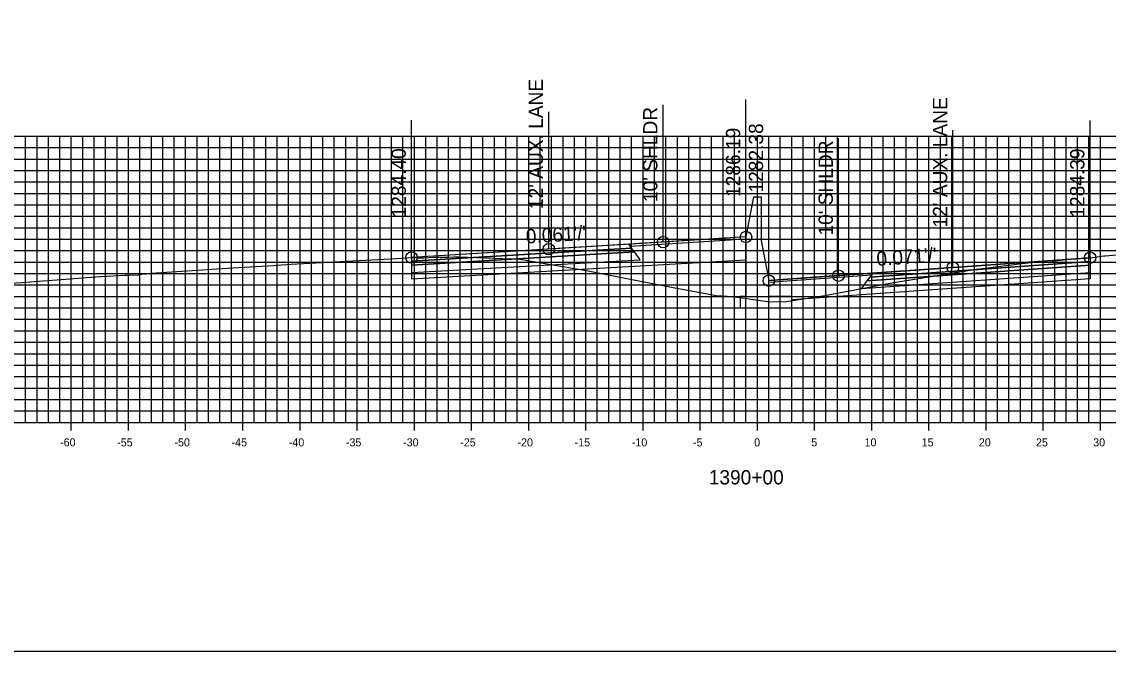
# Model space of a CAD drawing. Extents: x 674939 to 678919, y 750652 to 765176.
# Drawn here: x 678674.2 to 678769.2, y 755752.6 to 755807.6 of the extents above; entities that cross this region are included whole.
import ezdxf

# ---------------------------------------------------------------- set-up
doc = ezdxf.new("R2010")
doc.units = 0
for name, color, linetype in [('R_Alt Surface', 7, 'Continuous'), ('R_Axis', 7, 'Continuous'), ('R_Axis Annot', 7, 'Continuous'), ('R_Exist Surface', 7, 'Continuous'), ('R_Fin Surface', 7, 'Continuous'), ('R_Grid', 7, 'Continuous'), ('R_No Plot', 7, 'Continuous'), ('R_Proposed Road', 7, 'Continuous'), ('R_Xsect Elev', 7, 'Continuous'), ('R_Xsect Slope', 7, 'Continuous')]:
    doc.layers.add(name, color=color, linetype=linetype)

msp = doc.modelspace()

# ---------------------------------------------------------------- linework, layer by layer
at = {"layer": 'R_Alt Surface'}
for points in [[(678708.288, 755786.621), (678708.288, 755786.291), (678727.788, 755787.437), (678727.538, 755787.777)], [(678708.288, 755786.291), (678708.288, 755785.631), (678728.288, 755786.757), (678727.788, 755787.437)], [(678767.633, 755786.277), (678767.633, 755785.617), (678747.633, 755784.223), (678748.133, 755784.903)], [(678767.633, 755786.607), (678767.633, 755786.277), (678748.133, 755784.903), (678748.383, 755785.243)]]:
    msp.add_lwpolyline(points, close=True, dxfattribs=at)
for points in [[(678708.288, 755785.631), (678708.288, 755785.091), (678728.288, 755786.217)], [(678728.288, 755786.217), (678737.533, 755786.737)], [(678767.633, 755785.617), (678767.635, 755785.077), (678747.633, 755783.683)], [(678747.633, 755783.683), (678741.533, 755783.258)]]:
    msp.add_lwpolyline(points, dxfattribs=at)
at = {"layer": 'R_Axis'}
for p, q in [((678678.533, 755771.851), (678678.533, 755773.251)), ((678683.533, 755771.851), (678683.533, 755773.251)), ((678688.533, 755771.851), (678688.533, 755773.251)), ((678693.533, 755771.851), (678693.533, 755773.251)), ((678698.533, 755771.851), (678698.533, 755773.251)), ((678703.533, 755771.851), (678703.533, 755773.251)), ((678708.533, 755771.851), (678708.533, 755773.251)), ((678713.533, 755771.851), (678713.533, 755773.251)), ((678718.533, 755771.851), (678718.533, 755773.251)), ((678723.533, 755771.851), (678723.533, 755773.251)), ((678728.533, 755771.851), (678728.533, 755773.251)), ((678733.533, 755771.851), (678733.533, 755773.251)), ((678738.533, 755771.851), (678738.533, 755773.251)), ((678743.533, 755771.851), (678743.533, 755773.251)), ((678748.533, 755771.851), (678748.533, 755773.251)), ((678753.533, 755771.851), (678753.533, 755773.251)), ((678758.533, 755771.851), (678758.533, 755773.251)), ((678763.533, 755771.851), (678763.533, 755773.251)), ((678768.533, 755771.851), (678768.533, 755773.251)), ((678638.533, 755772.551), (678838.533, 755772.551))]:
    msp.add_line(p, q, dxfattribs=at)
at = {"layer": 'R_Exist Surface'}
msp.add_lwpolyline([(678673.14, 755784.719), (678674.273, 755784.782), (678674.496, 755784.805), (678678.046, 755785.064), (678679.84, 755785.197), (678681.116, 755785.282), (678683.24, 755785.414), (678683.616, 755785.424), (678684.365, 755785.451), (678684.741, 755785.489), (678685.122, 755785.53), (678685.274, 755785.545), (678685.515, 755785.57), (678689.115, 755785.817), (678691.696, 755785.985), (678694.663, 755786.16), (678696.269, 755786.26), (678696.516, 755786.28), (678697.748, 755786.363), (678701.523, 755786.574), (678707.514, 755786.908), (678708.288, 755786.951), (678708.292, 755786.951), (678708.439, 755786.96), (678708.805, 755786.934), (678709.35, 755786.928), (678710.205, 755786.968), (678710.595, 755786.986), (678711.448, 755786.994), (678711.995, 755787.001), (678712.32, 755787.001), (678712.424, 755787.004), (678716.253, 755786.868), (678717.771, 755786.809), (678718.766, 755786.644), (678723.748, 755785.775), (678727.11, 755785.112), (678731.173, 755784.334), (678734.932, 755783.62), (678736.385, 755783.554), (678739.626, 755783.074), (678741.069, 755783.108), (678744.445, 755783.623), (678750.294, 755784.75), (678756.263, 755785.709), (678757.67, 755785.939), (678758.226, 755786.002), (678761.661, 755786.416), (678764.041, 755786.695), (678764.053, 755786.695), (678764.491, 755786.644), (678764.578, 755786.653), (678765.516, 755786.767), (678765.555, 755786.771), (678765.58, 755786.772), (678767.264, 755786.889), (678767.329, 755786.897), (678767.633, 755786.937), (678768.822, 755787.098), (678768.944, 755787.112), (678773.028, 755787.435)], dxfattribs=at)
at = {"layer": 'R_Fin Surface'}
for points in [[(678737.533, 755788.745), (678730.288, 755788.301), (678720.288, 755787.687), (678708.288, 755786.951)], [(678767.633, 755786.937), (678755.633, 755786.082), (678745.633, 755785.369), (678739.533, 755784.934)]]:
    msp.add_lwpolyline(points, dxfattribs=at)
for points in [[(678708.288, 755786.951), (678708.288, 755786.621), (678727.538, 755787.777), (678727.288, 755788.117)], [(678727.406, 755787.956), (678737.533, 755788.585), (678737.533, 755788.745), (678727.288, 755788.117)], [(678767.633, 755786.937), (678767.633, 755786.607), (678748.383, 755785.243), (678748.633, 755785.583)], [(678748.515, 755785.423), (678739.533, 755784.774), (678739.533, 755784.934), (678748.633, 755785.583)]]:
    msp.add_lwpolyline(points, close=True, dxfattribs=at)
at = {"layer": 'R_Grid'}
for p, q in [((678638.533, 755797.551), (678838.533, 755797.551)), ((678674.533, 755772.551), (678674.533, 755797.551)), ((678675.533, 755772.551), (678675.533, 755797.551)), ((678676.533, 755772.551), (678676.533, 755797.551)), ((678677.533, 755772.551), (678677.533, 755797.551)), ((678678.533, 755772.551), (678678.533, 755797.551)), ((678679.533, 755772.551), (678679.533, 755797.551)), ((678680.533, 755772.551), (678680.533, 755797.551)), ((678681.533, 755772.551), (678681.533, 755797.551)), ((678682.533, 755772.551), (678682.533, 755797.551)), ((678683.533, 755772.551), (678683.533, 755797.551)), ((678684.533, 755772.551), (678684.533, 755797.551)), ((678685.533, 755772.551), (678685.533, 755797.551)), ((678686.533, 755772.551), (678686.533, 755797.551)), ((678687.533, 755772.551), (678687.533, 755797.551)), ((678688.533, 755772.551), (678688.533, 755797.551)), ((678689.533, 755772.551), (678689.533, 755797.551)), ((678690.533, 755772.551), (678690.533, 755797.551)), ((678691.533, 755772.551), (678691.533, 755797.551)), ((678692.533, 755772.551), (678692.533, 755797.551)), ((678693.533, 755772.551), (678693.533, 755797.551)), ((678694.533, 755772.551), (678694.533, 755797.551)), ((678695.533, 755772.551), (678695.533, 755797.551)), ((678696.533, 755772.551), (678696.533, 755797.551)), ((678697.533, 755772.551), (678697.533, 755797.551)), ((678698.533, 755772.551), (678698.533, 755797.551)), ((678699.533, 755772.551), (678699.533, 755797.551)), ((678700.533, 755772.551), (678700.533, 755797.551)), ((678701.533, 755772.551), (678701.533, 755797.551)), ((678702.533, 755772.551), (678702.533, 755797.551)), ((678703.533, 755772.551), (678703.533, 755797.551)), ((678704.533, 755772.551), (678704.533, 755797.551)), ((678705.533, 755772.551), (678705.533, 755797.551)), ((678706.533, 755772.551), (678706.533, 755797.551)), ((678707.533, 755772.551), (678707.533, 755797.551)), ((678708.533, 755772.551), (678708.533, 755797.551)), ((678709.533, 755772.551), (678709.533, 755797.551)), ((678710.533, 755772.551), (678710.533, 755797.551)), ((678711.533, 755772.551), (678711.533, 755797.551)), ((678712.533, 755772.551), (678712.533, 755797.551)), ((678713.533, 755772.551), (678713.533, 755797.551)), ((678714.533, 755772.551), (678714.533, 755797.551)), ((678715.533, 755772.551), (678715.533, 755797.551)), ((678716.533, 755772.551), (678716.533, 755797.551)), ((678717.533, 755772.551), (678717.533, 755797.551)), ((678718.533, 755772.551), (678718.533, 755797.551)), ((678719.533, 755772.551), (678719.533, 755797.551)), ((678720.533, 755772.551), (678720.533, 755797.551)), ((678721.533, 755772.551), (678721.533, 755797.551)), ((678722.533, 755772.551), (678722.533, 755797.551)), ((678723.533, 755772.551), (678723.533, 755797.551)), ((678724.533, 755772.551), (678724.533, 755797.551)), ((678725.533, 755772.551), (678725.533, 755797.551)), ((678726.533, 755772.551), (678726.533, 755797.551)), ((678727.533, 755772.551), (678727.533, 755797.551)), ((678728.533, 755772.551), (678728.533, 755797.551)), ((678729.533, 755772.551), (678729.533, 755797.551)), ((678730.533, 755772.551), (678730.533, 755797.551)), ((678731.533, 755772.551), (678731.533, 755797.551)), ((678732.533, 755772.551), (678732.533, 755797.551)), ((678733.533, 755772.551), (678733.533, 755797.551)), ((678734.533, 755772.551), (678734.533, 755797.551)), ((678735.533, 755772.551), (678735.533, 755797.551)), ((678736.533, 755772.551), (678736.533, 755797.551)), ((678737.533, 755772.551), (678737.533, 755797.551)), ((678738.533, 755772.551), (678738.533, 755797.551)), ((678739.533, 755772.551), (678739.533, 755797.551)), ((678740.533, 755772.551), (678740.533, 755797.551)), ((678741.533, 755772.551), (678741.533, 755797.551)), ((678742.533, 755772.551), (678742.533, 755797.551)), ((678743.533, 755772.551), (678743.533, 755797.551)), ((678744.533, 755772.551), (678744.533, 755797.551)), ((678745.533, 755772.551), (678745.533, 755797.551)), ((678746.533, 755772.551), (678746.533, 755797.551)), ((678747.533, 755772.551), (678747.533, 755797.551)), ((678748.533, 755772.551), (678748.533, 755797.551)), ((678749.533, 755772.551), (678749.533, 755797.551)), ((678750.533, 755772.551), (678750.533, 755797.551)), ((678751.533, 755772.551), (678751.533, 755797.551)), ((678752.533, 755772.551), (678752.533, 755797.551)), ((678753.533, 755772.551), (678753.533, 755797.551)), ((678754.533, 755772.551), (678754.533, 755797.551)), ((678755.533, 755772.551), (678755.533, 755797.551)), ((678756.533, 755772.551), (678756.533, 755797.551)), ((678757.533, 755772.551), (678757.533, 755797.551)), ((678758.533, 755772.551), (678758.533, 755797.551)), ((678759.533, 755772.551), (678759.533, 755797.551)), ((678760.533, 755772.551), (678760.533, 755797.551)), ((678761.533, 755772.551), (678761.533, 755797.551)), ((678762.533, 755772.551), (678762.533, 755797.551)), ((678763.533, 755772.551), (678763.533, 755797.551)), ((678764.533, 755772.551), (678764.533, 755797.551)), ((678765.533, 755772.551), (678765.533, 755797.551)), ((678766.533, 755772.551), (678766.533, 755797.551)), ((678767.533, 755772.551), (678767.533, 755797.551)), ((678768.533, 755772.551), (678768.533, 755797.551)), ((678638.533, 755796.551), (678838.533, 755796.551)), ((678638.533, 755795.551), (678838.533, 755795.551)), ((678638.533, 755794.551), (678838.533, 755794.551)), ((678638.533, 755793.551), (678838.533, 755793.551)), ((678638.533, 755792.551), (678838.533, 755792.551)), ((678638.533, 755791.551), (678838.533, 755791.551)), ((678638.533, 755790.551), (678838.533, 755790.551)), ((678638.533, 755789.551), (678838.533, 755789.551)), ((678638.533, 755788.551), (678838.533, 755788.551)), ((678638.533, 755787.551), (678838.533, 755787.551)), ((678638.533, 755786.551), (678838.533, 755786.551)), ((678638.533, 755785.551), (678838.533, 755785.551)), ((678638.533, 755784.551), (678838.533, 755784.551)), ((678638.533, 755783.551), (678838.533, 755783.551)), ((678638.533, 755782.551), (678838.533, 755782.551)), ((678638.533, 755781.551), (678838.533, 755781.551)), ((678638.533, 755780.551), (678838.533, 755780.551)), ((678638.533, 755779.551), (678838.533, 755779.551)), ((678638.533, 755778.551), (678838.533, 755778.551)), ((678638.533, 755777.551), (678838.533, 755777.551)), ((678638.533, 755776.551), (678838.533, 755776.551)), ((678638.533, 755775.551), (678838.533, 755775.551)), ((678638.533, 755774.551), (678838.533, 755774.551)), ((678638.533, 755773.551), (678838.533, 755773.551)), ((678638.533, 755772.551), (678838.533, 755772.551))]:
    msp.add_line(p, q, dxfattribs=at)
at = {"layer": 'R_No Plot'}
msp.add_lwpolyline([(678578.533, 755752.551), (678918.533, 755752.551), (678918.533, 755972.551), (678578.533, 755972.551)], close=True, dxfattribs=at)
for centre in [(678737.533, 755788.745), (678720.288, 755787.687), (678730.288, 755788.301), (678708.288, 755786.951), (678767.633, 755786.937), (678755.633, 755786.082), (678739.533, 755784.934), (678745.633, 755785.369)]:
    msp.add_circle(centre, 0.5, dxfattribs=at)
at = {"layer": 'R_Proposed Road'}
for points in [[(678738.203, 755792.245), (678737.533, 755788.745)], [(678738.203, 755792.245), (678738.203, 755792.245)], [(678738.203, 755792.245), (678738.863, 755792.245)], [(678738.863, 755792.245), (678738.863, 755788.434)], [(678737.533, 755788.745), (678737.533, 755783.559), (678737.033, 755783.559), (678737.033, 755782.559), (678741.533, 755782.559), (678741.533, 755783.559), (678739.533, 755783.559), (678739.533, 755784.934)], [(678738.863, 755788.434), (678739.533, 755784.934)]]:
    msp.add_lwpolyline(points, dxfattribs=at)
at = {"layer": 'R_Xsect Elev'}
for p, q in [((678737.533, 755788.745), (678737.533, 755800.745)), ((678720.288, 755787.687), (678720.288, 755799.687)), ((678730.288, 755788.301), (678730.288, 755800.301)), ((678708.288, 755786.951), (678708.288, 755798.951)), ((678767.633, 755786.937), (678767.633, 755798.937)), ((678755.633, 755786.082), (678755.633, 755798.082)), ((678739.533, 755784.934), (678739.533, 755796.934)), ((678745.633, 755785.369), (678745.633, 755797.369))]:
    msp.add_line(p, q, dxfattribs=at)

# ---------------------------------------------------------------- texts
at = {"layer": 'R_Axis Annot'}
for s, height, p in [('-60', 0.7, (678677.552, 755770.451)), ('-55', 0.7, (678682.546, 755770.451)), ('-50', 0.7, (678687.552, 755770.451)), ('-45', 0.7, (678692.546, 755770.451)), ('-40', 0.7, (678697.552, 755770.451)), ('-35', 0.7, (678702.546, 755770.451)), ('-30', 0.7, (678707.552, 755770.451)), ('-25', 0.7, (678712.546, 755770.451)), ('-20', 0.7, (678717.552, 755770.451)), ('-15', 0.7, (678722.546, 755770.451)), ('-10', 0.7, (678727.552, 755770.451)), ('-5', 0.7, (678732.896, 755770.451)), ('0', 0.7, (678738.252, 755770.451)), ('5', 0.7, (678743.246, 755770.451)), ('10', 0.7, (678747.902, 755770.451)), ('15', 0.7, (678752.896, 755770.451)), ('20', 0.7, (678757.902, 755770.451)), ('25', 0.7, (678762.896, 755770.451)), ('30', 0.7, (678767.902, 755770.451)), ('1390+00', 1.25, (678734.281, 755767.126))]:
    msp.add_text(s, height=height, dxfattribs=at).set_placement(p)
at = {"layer": 'R_Xsect Elev'}
for s, p in [("12' AUX. LANE", (678719.788, 755791.187)), ("12' AUX. LANE", (678755.133, 755789.582)), ("10' SHLDR", (678729.788, 755791.801)), ('1282.38', (678739.033, 755792.632)), ('1286.19', (678737.033, 755792.245)), ("10' SHLDR", (678745.133, 755788.869)), ('1284.40', (678707.788, 755790.451)), ('1284.39', (678767.133, 755790.437))]:
    msp.add_text(s, height=1.25, rotation=90, dxfattribs=at).set_placement(p)
at = {"layer": 'R_Xsect Slope'}
for s, rotation, p in [("0.061'/'", 3.51094, (678718.32, 755788.168)), ("0.071'/'", 4.07648, (678748.989, 755786.21))]:
    msp.add_text(s, height=1.25, rotation=rotation, dxfattribs=at).set_placement(p)

doc.saveas('drawing.dxf')
